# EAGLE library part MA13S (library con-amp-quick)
AMP QUICK CONNECTOR
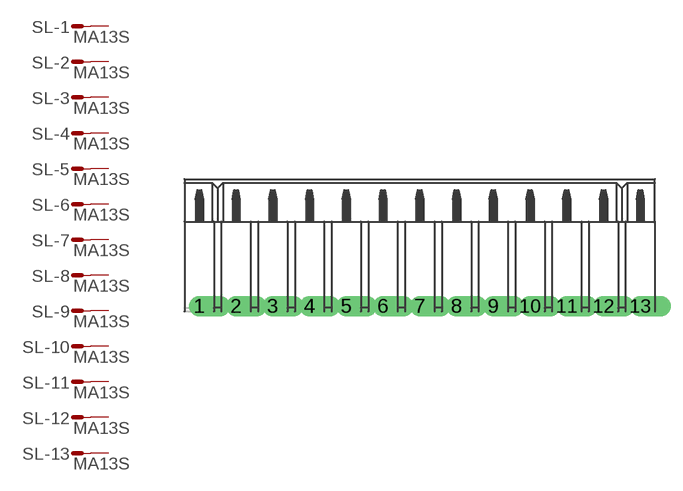
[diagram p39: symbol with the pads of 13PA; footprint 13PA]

Designator prefix SL; gates -1=M -2=M -3=M -4=M -5=M -6=M -7=M -8=M -9=M -10=M -11=M -12=M -13=M

## MA13S  [13PA]
1  -1:S  pas
2  -2:S  pas
3  -3:S  pas
4  -4:S  pas
5  -5:S  pas
6  -6:S  pas
7  -7:S  pas
8  -8:S  pas
9  -9:S  pas
10  -10:S  pas
11  -11:S  pas
12  -12:S  pas
13  -13:S  pas

## Footprint 13PA (pad centres in mm)
AMP QUICK CONNECTOR
drill 0.914 offset: 1 -15.24,0; 2 -12.7,0; 3 -10.16,0; 4 -7.62,0; 5 -5.08,0; 6 -2.54,0; 7 0,0; 8 2.54,0; 9 5.08,0; 10 7.62,0; 11 10.16,0; 12 12.7,0; 13 15.24,0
